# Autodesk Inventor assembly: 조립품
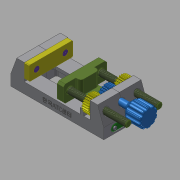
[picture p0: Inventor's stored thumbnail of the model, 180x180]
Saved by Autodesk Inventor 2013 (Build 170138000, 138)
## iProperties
Created: 2017-04
Part Number: 조립품
Document SubType Name: Assembly
Designer: mduedu
Author: mduedu
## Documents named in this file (10)
- D:\010_ATC_시험관련\INVENTOR\정시\20170422\1급\완성품\조립품.iam
- D:\010_ATC_시험관련\INVENTOR\정시\20170422\1급\완성품\바이스본체 A.ipt
- D:\010_ATC_시험관련\INVENTOR\정시\20170422\1급\완성품\바이스본체 B.ipt
- D:\010_ATC_시험관련\INVENTOR\정시\20170422\1급\완성품\고정 플레이트.ipt
- D:\010_ATC_시험관련\INVENTOR\정시\20170422\1급\완성품\슬라이딩 부품.ipt
- D:\010_ATC_시험관련\INVENTOR\정시\20170422\1급\완성품\핸들.ipt
- D:\010_ATC_시험관련\INVENTOR\정시\20170422\1급\완성품\스퍼기어.ipt
- D:\010_ATC_시험관련\INVENTOR\정시\20170422\1급\완성품\지지대.ipt
- D:\010_ATC_시험관련\INVENTOR\정시\20170422\1급\완성품\십자오목머리나사 M4.ipt
- D:\010_ATC_시험관련\INVENTOR\정시\20170422\1급\완성품\십자오목머리나사 M3.ipt
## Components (3 placed, 2 different names)
1. 고정 플레이트:1
2. 고정 플레이트:2
3. 핸들:1 — 구동부
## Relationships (1: Angle 1)
- 구동부 [Angle]: 핸들:1
